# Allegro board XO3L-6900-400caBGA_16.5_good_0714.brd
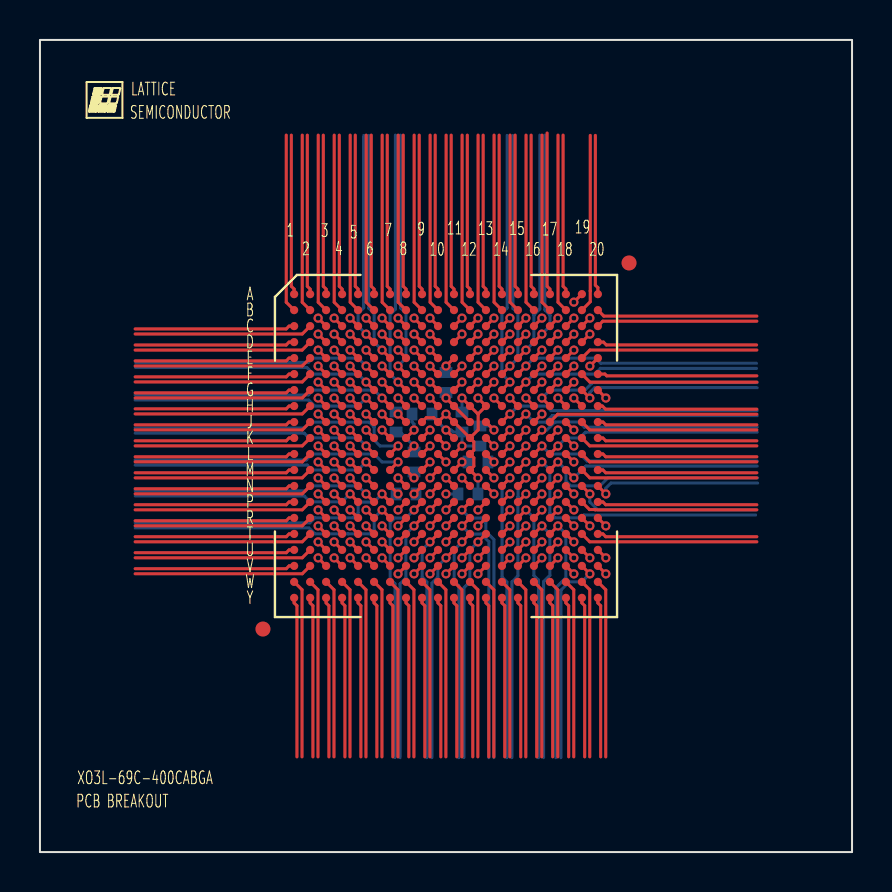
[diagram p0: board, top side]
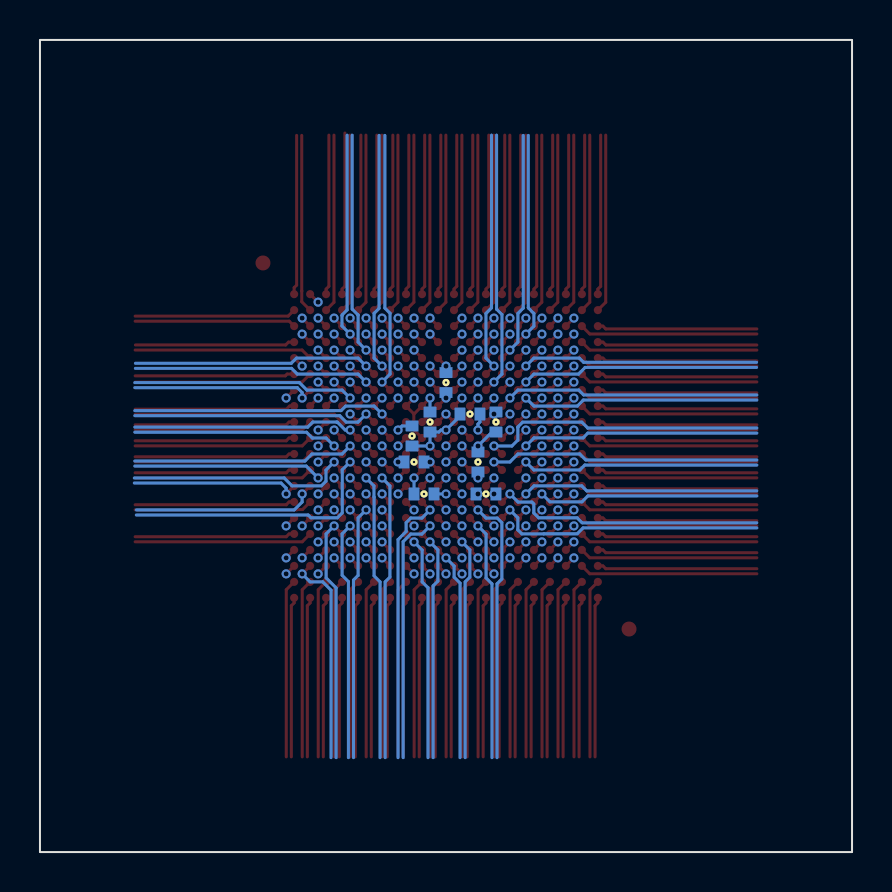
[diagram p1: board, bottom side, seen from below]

Outline 40.64 x 40.64 mm; copper layers: TOP, L2_GND, L3_SIGNAL, L4_SIGNAL, L5_PWR, BOTTOM. Coordinates in mm from the lower left corner of the outline.
Outline path: rectangle 0,0 40.64,40.64

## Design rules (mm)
net group CDPB4: nets PB4C PB4D
net group CDPB6: nets PB6C PB6D
net group CDPB7: nets PB7C PB7D
net group CDPB9: nets PB9C PB9D
net group CDPB10: nets PB10C PB10D
net group CDPB12: nets PB12C PB12D
net group CDPB13: nets PB13C PB13D
net group CDPB15: nets PB15C PB15D
net group CDPB16: nets PB16C PB16D
net group CDPB18: nets PB18C PB18D
net group CDPB21: nets PB21C PB21D
net group CDPB23: nets PB23C PB23D
net group CDPB26: nets PB26C PB26D
net group CDPB28: nets PB28C PB28D
net group CDPB29: nets PB29C PB29D
net group CDPB31: nets PB31C PB31D
net group CDPB32: nets PB32C PB32D
net group CDPB34: nets PB34C PB34D
net group CDPB35: nets PB35C PB35D
net group CDPB37: nets PB37C PB37D
net group CDPB38: nets PB38C PB38D
net group CDPL2: nets PL2C PL2D
net group CDPL3: nets PL3C PL3D
net group CDPL4: nets PL4C PL4D
net group CDPL5: nets PL5C PL5D
net group CDPL6: nets PL6C PL6D
net group CDPL7: nets PL7C PL7D
net group CDPL8: nets PL8C PL8D
net group CDPL9: nets PL9C PL9D
net group CDPL10: nets PL10C PL10D
net group CDPL11: nets PL11C PL11D
net group CDPL12: nets PL12C PL12D
net group CDPL14: nets PL14C PL14D
net group CDPL15: nets PL15C PL15D
net group CDPL16: nets PL16C PL16D
net group CDPL17: nets PL17C PL17D
net group CDPL18: nets PL18C PL18D
net group CDPL19: nets PL19C PL19D
net group CDPL20: nets PL20C PL20D
net group CDPL21: nets PL21C PL21D
net group CDPL22: nets PL22C PL22D
net group CDPL23: nets PL23C PL23D
net group CDPL24: nets PL24C PL24D
net group CDPL25: nets PL25C PL25D
net group CDPL26: nets PL26C PL26D
net group CDPL29: nets PL29C PL29D
net group CDPL32: nets PL32C PL32D
net group CDPL35: nets PL35C PL35D
net group CDPL38: nets PL38C PL38D
net group CDPL41: nets PL41C PL41D
net group CDPL44: nets PL44C PL44D
net group CDPL47: nets PL47C PL47D
net group CDPL50: nets PL50C PL50D
net group CDPL53: nets PL53C PL53D
net group CDPL56: nets PL56C PL56D
net group CDPL59: nets PL59C PL59D
net group CDPL62: nets PL62C PL62D
net group CDPL65: nets PL65C PL65D
net group CDPL68: nets PL68C PL68D
net group CDPL71: nets PL71C PL71D
net group CDPL74: nets PL74C PL74D
net group CDPL77: nets PL77C PL77D
net group CDPL80: nets PL80C PL80D
net group CDPL83: nets PL83C PL83D
net group CDPL86: nets PL86C PL86D
net group CDPL89: nets PL89C PL89D
net group CDPL92: nets PL92C PL92D
net group CDPR2: nets PR2C PR2D
net group CDPR3: nets PR3C PR3D
net group CDPR4: nets PR4C PR4D
net group CDPR5: nets PR5C PR5D
net group CDPR6: nets PR6C PR6D
net group CDPR7: nets PR7C PR7D
net group CDPR8: nets PR8C PR8D
net group CDPR9: nets PR9C PR9D
net group CDPR10: nets PR10C PR10D
net group CDPR11: nets PR11C PR11D
net group CDPR12: nets PR12C PR12D
net group CDPR14: nets PR14C PR14D
net group CDPR15: nets PR15C PR15D
net group CDPR16: nets PR16C PR16D
net group CDPR17: nets PR17C PR17D
net group CDPR18: nets PR18C PR18D
net group CDPR19: nets PR19C PR19D
net group CDPR20: nets PR20C PR20D
net group CDPR21: nets PR21C PR21D
net group CDPR22: nets PR22C PR22D
net group CDPR23: nets PR23C PR23D
net group CDPR24: nets PR24C PR24D
net group CDPR25: nets PR25C PR25D
net group CDPR26: nets PR26C PR26D
net group CDPR29: nets PR29C PR29D
net group CDPR32: nets PR32C PR32D
net group CDPR35: nets PR35C PR35D
net group CDPR38: nets PR38C PR38D
net group CDPR41: nets PR41C PR41D
net group CDPR44: nets PR44C PR44D
net group CDPR47: nets PR47C PR47D
net group CDPR50: nets PR50C PR50D
net group CDPR53: nets PR53C PR53D
net group CDPR56: nets PR56C PR56D
net group CDPR59: nets PR59C PR59D
net group CDPR62: nets PR62C PR62D
net group CDPR65: nets PR65C PR65D
net group CDPR68: nets PR68C PR68D
net group CDPR71: nets PR71C PR71D
net group CDPR74: nets PR74C PR74D
net group CDPR77: nets PR77C PR77D
net group CDPR80: nets PR80C PR80D
net group CDPR83: nets PR83C PR83D
net group CDPR86: nets PR86C PR86D
net group CDPR89: nets PR89C PR89D
net group CDPR92: nets PR92C PR92D
net group CDPT9: nets PT9C PT9D
net group CDPT10: nets PT10C PT10D
net group CDPT11: nets PT11C PT11D
net group CDPT12: nets PT12C PT12D
net group CDPT13: nets PT13C PT13D
net group CDPT14: nets PT14C PT14D
net group CDPT15: nets PT15C PT15D
net group CDPT16: nets PT16C PT16D
net group CDPT17: nets PT17C PT17D
net group CDPT18: nets PT18C PT18D
net group CDPT21: nets PT21C PT21D
net group CDPT22: nets PT22C PT22D
net group CDPT25: nets PT25C PT25D
net group CDPT26: nets PT26C PT26D
net group CDPT27: nets PT27C PT27D
net group CDPT28: nets PT28C PT28D
net group CDPT32: nets PT32C PT32D
net group CDPT33: nets PT33C PT33D
net group CDPT34: nets PT34C PT34D
net group CDPT35: nets PT35C PT35D
net group CDPT36: nets PT36C PT36D
net group PB4: nets PB4A PB4B
net group PB6: nets PB6A PB6B
net group PB7: nets PB7A PB7B
net group PB9: nets PB9A PB9B
net group PB10: nets PB10A PB10B
net group PB12: nets PB12A PB12B
net group PB13: nets PB13A PB13B
net group PB15: nets PB15A PB15B
net group PB16: nets PB16A PB16B
net group PB18: nets PB18A PB18B
net group PB21: nets PB21A PB21B
net group PB23: nets PB23A PB23B
net group PB26: nets PB26A PB26B
net group PB28: nets PB28A PB28B
net group PB29: nets PB29A PB29B
net group PB31: nets PB31A PB31B
net group PB32: nets PB32A PB32B
net group PB34: nets PB34A PB34B
net group PB35: nets PB35A PB35B
net group PB37: nets PB37A PB37B
net group PB38: nets PB38A PB38B
net group PB98: nets PB98A PB98B
net group PL2: nets PL2A PL2B
net group PL3: nets PL3A PL3B
net group PL4: nets PL4A PL4B
net group PL5: nets PL5A PL5B
net group PL6: nets PL6A PL6B
net group PL7: nets PL7A PL7B
net group PL8: nets PL8A PL8B
net group PL9: nets PL9A PL9B
net group PL10: nets PL10A PL10B
net group PL11: nets PL11A PL11B
net group PL12: nets PL12A PL12B
net group PL14: nets PL14A PL14B
net group PL15: nets PL15A PL15B
net group PL16: nets PL16A PL16B
net group PL17: nets PL17A PL17B
net group PL18: nets PL18A PL18B
net group PL19: nets PL19A PL19B
net group PL20: nets PL20A PL20B
net group PL21: nets PL21A PL21B
net group PL22: nets PL22A PL22B
net group PL23: nets PL23A PL23B
net group PL24: nets PL24A PL24B
net group PL25: nets PL25A PL25B
net group PL29: nets PL29A PL29B
net group PL32: nets PL32A PL32B
net group PL35: nets PL35A PL35B
net group PL38: nets PL38A PL38B
net group PL41: nets PL41A PL41B
net group PL44: nets PL44A PL44B
net group PL47: nets PL47A PL47B
net group PL50: nets PL50A PL50B
net group PL53: nets PL53A PL53B
net group PL56: nets PL56A PL56B
net group PL59: nets PL59A PL59B
net group PL62: nets PL62A PL62B
net group PL65: nets PL65A PL65B
net group PL68: nets PL68A PL68B
net group PL71: nets PL71A PL71B
net group PL74: nets PL74A PL74B
net group PL77: nets PL77A PL77B
net group PL80: nets PL80A PL80B
net group PL83: nets PL83A PL83B
net group PL86: nets PL86A PL86B
net group PL89: nets PL89A PL89B
net group PL92: nets PL92A PL92B
net group PR2: nets PR2A PR2B
net group PR3: nets PR3A PR3B
net group PR4: nets PR4A PR4B
net group PR5: nets PR5A PR5B
net group PR6: nets PR6A PR6B
net group PR7: nets PR7A PR7B
net group PR8: nets PR8A PR8B
net group PR9: nets PR9A PR9B
net group PR10: nets PR10A PR10B
net group PR11: nets PR11A PR11B
net group PR12: nets PR12A PR12B
net group PR14: nets PR14A PR14B
net group PR15: nets PR15A PR15B
net group PR16: nets PR16A PR16B
net group PR17: nets PR17A PR17B
net group PR18: nets PR18A PR18B
net group PR19: nets PR19A PR19B
net group PR20: nets PR20A PR20B
net group PR21: nets PR21A PR21B
net group PR22: nets PR22A PR22B
net group PR23: nets PR23A PR23B
net group PR24: nets PR24A PR24B
net group PR25: nets PR25A PR25B
net group PR26: nets PR26A PR26B
net group PR29: nets PR29A PR29B
net group PR32: nets PR32A PR32B
net group PR35: nets PR35A PR35B
net group PR38: nets PR38A PR38B
net group PR41: nets PR41A PR41B
net group PR44: nets PR44A PR44B
net group PR47: nets PR47A PR47B
net group PR50: nets PR50A PR50B
net group PR53: nets PR53A PR53B
net group PR56: nets PR56A PR56B
net group PR59: nets PR59A PR59B
net group PR62: nets PR62A PR62B
net group PR65: nets PR65A PR65B
net group PR68: nets PR68A PR68B
net group PR71: nets PR71A PR71B
net group PR74: nets PR74A PR74B
net group PR77: nets PR77A PR77B
net group PR80: nets PR80A PR80B
net group PR83: nets PR83A PR83B
net group PR86: nets PR86A PR86B
net group PR89: nets PR89A PR89B
net group PR92: nets PR92A PR92B
net group PT4: nets PT4A PT4B
net group PT6: nets PT6A PT6B
net group PT9: nets PT9A PT9B
net group PT10: nets PT10A PT10B
net group PT11: nets PT11A PT11B
net group PT12: nets PT12A PT12B
net group PT13: nets PT13A PT13B
net group PT14: nets PT14A PT14B
net group PT15: nets PT15A PT15B
net group PT16: nets PT16A PT16B
net group PT17: nets PT17A PT17B
net group PT18: nets PT18A PT18B
net group PT20: nets PT20A PT20B
net group PT21: nets PT21A PT21B
net group PT22: nets PT22A PT22B
net group PT24: nets PT24A PT24B
net group PT25: nets PT25A PT25B
net group PT26: nets PT26A PT26B
net group PT27: nets PT27A PT27B
net group PT28: nets PT28A PT28B
net group PT29: nets PT29A PT29B
net group PT31: nets PT31A PT31B
net group PT32: nets PT32A PT32B
net group PT33: nets PT33A PT33B
net group PT34: nets PT34A PT34B
net group PT35: nets PT35A PT35B
net group PT36: nets PT36A PT36B
net group PT38: nets PT38A PT38B
net group PT40: nets PT40A PT40B
net group PT42: nets PT42A PT42B
net group PT44: nets PT44A PT44B
net group PT45: nets PT45A PT45B
net group PT47: nets PT47A PT47B
net group PT49: nets PT49A PT49B
net group PT51: nets PT51A PT51B
net group PT54: nets PT54A PT54B
net group PT56: nets PT56A PT56B
net group PT58: nets PT58A PT58B
net group PT60: nets PT60A PT60B
net group PT63: nets PT63A PT63B
net group PT65: nets PT65A PT65B
net group PT69: nets PT69A PT69B
net group PT71: nets PT71A PT71B
net group PT74: nets PT74A PT74B
net group PT76: nets PT76A PT76B
net group PT101: nets PT101A PT101B
net group PT103: nets PT103A PT103B
net group PT105: nets PT105A PT105B
net group PT107: nets PT107A PT107B
net group PT110: nets PT110A PT110B
net group PT112: nets PT112A PT112B
net group PT114: nets PT114A PT114B
net group PT116: nets PT116A PT116B
net group PT119: nets PT119A PT119B
net group PT121: nets PT121A PT121B

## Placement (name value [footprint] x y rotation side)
BGA  -  [BGA400C80P20X20_1700X1700X13-1]  20.32 20.32 270 top
C1  VAL  [C0402]  20.32 23.5 270 bottom
C2  VAL  [C0402]  18.32 17.92 0 bottom
C3  VAL  [C0402]  17.82 21.52 90 bottom
C4  VAL  [C0402]  21.12 21.52 270 bottom
C5  VAL  [C0402]  21.92 19.52 180 bottom
C6  VAL  [C0402]  22.02 20.82 90 bottom
C7  VAL  [C0402]  21.42 17.92 180 bottom
C11  VAL  [C0402]  18.72 19.52 90 bottom
C12  VAL  [C0402]  19.12 21.92 180 bottom
NOREF  -  []  24.69 13 0 top

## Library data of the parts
BGA = BGA400C80P20X20_1700X1700X13-1
C1 C4-C7 C11 C12 = C0402: Tolerance: TOL; User Part Number: UPN
C2 C3 = C0402: User Part Number: UPN; Tolerance: TOL

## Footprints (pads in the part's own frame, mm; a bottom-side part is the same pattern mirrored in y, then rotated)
BGA400C80P20X20_1700X1700X13-1
  round 0.75 smd: (-9.16,9.16) (9.16,-9.16)
  round 0.406 smd: A1(-7.6,-7.6) A2(-7.6,-6.8) A3(-7.6,-6) A4(-7.6,-5.2) A5(-7.6,-4.4) A6(-7.6,-3.6) A7(-7.6,-2.8) A8(-7.6,-2) A9(-7.6,-1.2) A10(-7.6,-0.4) A11(-7.6,0.4) A12(-7.6,1.2) A13(-7.6,2) A14(-7.6,2.8) A15(-7.6,3.6) A16(-7.6,4.4) A17(-7.6,5.2) A18(-7.6,6) A19(-7.6,6.8) A20(-7.6,7.6) B1(-6.8,-7.6) B2(-6.8,-6.8) B3(-6.8,-6) B4(-6.8,-5.2) B5(-6.8,-4.4) B6(-6.8,-3.6) B7(-6.8,-2.8) B8(-6.8,-2) B9(-6.8,-1.2) B10(-6.8,-0.4) B11(-6.8,0.4) B12(-6.8,1.2) B13(-6.8,2) B14(-6.8,2.8) B15(-6.8,3.6) B16(-6.8,4.4) B17(-6.8,5.2) B18(-6.8,6) B19(-6.8,6.8) B20(-6.8,7.6) C1(-6,-7.6) C2(-6,-6.8) C3(-6,-6) C4(-6,-5.2) C5(-6,-4.4) C6(-6,-3.6) C7(-6,-2.8) C8(-6,-2) C9(-6,-1.2) C10(-6,-0.4) C11(-6,0.4) C12(-6,1.2) C13(-6,2) C14(-6,2.8) C15(-6,3.6) C16(-6,4.4) C17(-6,5.2) C18(-6,6) C19(-6,6.8) C20(-6,7.6) D1(-5.2,-7.6) D2(-5.2,-6.8) D3(-5.2,-6) D4(-5.2,-5.2) D5(-5.2,-4.4) D6(-5.2,-3.6) D7(-5.2,-2.8) D8(-5.2,-2) D9(-5.2,-1.2) D10(-5.2,-0.4) D11(-5.2,0.4) D12(-5.2,1.2) D13(-5.2,2) D14(-5.2,2.8) D15(-5.2,3.6) D16(-5.2,4.4) D17(-5.2,5.2) D18(-5.2,6) D19(-5.2,6.8) D20(-5.2,7.6) E1(-4.4,-7.6) E2(-4.4,-6.8) E3(-4.4,-6) E4(-4.4,-5.2) E5(-4.4,-4.4) E6(-4.4,-3.6) E7(-4.4,-2.8) E8(-4.4,-2) E9(-4.4,-1.2) E10(-4.4,-0.4) E11(-4.4,0.4) E12(-4.4,1.2) E13(-4.4,2) E14(-4.4,2.8) E15(-4.4,3.6) E16(-4.4,4.4) E17(-4.4,5.2) E18(-4.4,6) E19(-4.4,6.8) E20(-4.4,7.6) F1(-3.6,-7.6) F2(-3.6,-6.8) F3(-3.6,-6) F4(-3.6,-5.2) F5(-3.6,-4.4) F6(-3.6,-3.6) F7(-3.6,-2.8) F8(-3.6,-2) F9(-3.6,-1.2) F10(-3.6,-0.4) F11(-3.6,0.4) F12(-3.6,1.2) F13(-3.6,2) F14(-3.6,2.8) F15(-3.6,3.6) F16(-3.6,4.4) F17(-3.6,5.2) F18(-3.6,6) F19(-3.6,6.8) F20(-3.6,7.6) G1(-2.8,-7.6) G2(-2.8,-6.8) G3(-2.8,-6) G4(-2.8,-5.2) G5(-2.8,-4.4) G6(-2.8,-3.6) G7(-2.8,-2.8) G8(-2.8,-2) G9(-2.8,-1.2) G10(-2.8,-0.4) G11(-2.8,0.4) G12(-2.8,1.2) G13(-2.8,2) G14(-2.8,2.8) G15(-2.8,3.6) G16(-2.8,4.4) G17(-2.8,5.2) G18(-2.8,6) G19(-2.8,6.8) G20(-2.8,7.6) H1(-2,-7.6) H2(-2,-6.8) H3(-2,-6) H4(-2,-5.2) H5(-2,-4.4) H6(-2,-3.6) H7(-2,-2.8) H8(-2,-2) H9(-2,-1.2) H10(-2,-0.4) H11(-2,0.4) H12(-2,1.2) H13(-2,2) H14(-2,2.8) H15(-2,3.6) H16(-2,4.4) H17(-2,5.2) H18(-2,6) H19(-2,6.8) H20(-2,7.6) J1(-1.2,-7.6) J2(-1.2,-6.8) J3(-1.2,-6) J4(-1.2,-5.2) J5(-1.2,-4.4) J6(-1.2,-3.6) J7(-1.2,-2.8) J8(-1.2,-2) J9(-1.2,-1.2) J10(-1.2,-0.4) J11(-1.2,0.4) J12(-1.2,1.2) J13(-1.2,2) J14(-1.2,2.8) J15(-1.2,3.6) J16(-1.2,4.4) J17(-1.2,5.2) J18(-1.2,6) J19(-1.2,6.8) J20(-1.2,7.6) K1(-0.4,-7.6) K2(-0.4,-6.8) K3(-0.4,-6) K4(-0.4,-5.2) K5(-0.4,-4.4) K6(-0.4,-3.6) K7(-0.4,-2.8) K8(-0.4,-2) K9(-0.4,-1.2) K10(-0.4,-0.4) K11(-0.4,0.4) K12(-0.4,1.2) K13(-0.4,2) K14(-0.4,2.8) K15(-0.4,3.6) K16(-0.4,4.4) K17(-0.4,5.2) K18(-0.4,6) K19(-0.4,6.8) K20(-0.4,7.6) L1(0.4,-7.6) L2(0.4,-6.8) L3(0.4,-6) L4(0.4,-5.2) L5(0.4,-4.4) L6(0.4,-3.6) L7(0.4,-2.8) L8(0.4,-2) L9(0.4,-1.2) L10(0.4,-0.4) L11(0.4,0.4) L12(0.4,1.2) L13(0.4,2) L14(0.4,2.8) L15(0.4,3.6) L16(0.4,4.4) L17(0.4,5.2) L18(0.4,6) L19(0.4,6.8) L20(0.4,7.6) M1(1.2,-7.6) M2(1.2,-6.8) M3(1.2,-6) M4(1.2,-5.2) M5(1.2,-4.4) M6(1.2,-3.6) M7(1.2,-2.8) M8(1.2,-2) M9(1.2,-1.2) M10(1.2,-0.4) M11(1.2,0.4) M12(1.2,1.2) M13(1.2,2) M14(1.2,2.8) M15(1.2,3.6) M16(1.2,4.4) M17(1.2,5.2) M18(1.2,6) M19(1.2,6.8) M20(1.2,7.6) N1(2,-7.6) N2(2,-6.8) N3(2,-6) N4(2,-5.2) N5(2,-4.4) N6(2,-3.6) N7(2,-2.8) N8(2,-2) N9(2,-1.2) N10(2,-0.4) N11(2,0.4) N12(2,1.2) N13(2,2) N14(2,2.8) N15(2,3.6) N16(2,4.4) N17(2,5.2) N18(2,6) N19(2,6.8) N20(2,7.6) P1(2.8,-7.6) P2(2.8,-6.8) P3(2.8,-6) P4(2.8,-5.2) P5(2.8,-4.4) P6(2.8,-3.6) P7(2.8,-2.8) P8(2.8,-2) P9(2.8,-1.2) P10(2.8,-0.4) P11(2.8,0.4) P12(2.8,1.2) P13(2.8,2) P14(2.8,2.8) P15(2.8,3.6) P16(2.8,4.4) P17(2.8,5.2) P18(2.8,6) P19(2.8,6.8) P20(2.8,7.6) R1(3.6,-7.6) R2(3.6,-6.8) R3(3.6,-6) R4(3.6,-5.2) R5(3.6,-4.4) R6(3.6,-3.6) R7(3.6,-2.8) R8(3.6,-2) R9(3.6,-1.2) R10(3.6,-0.4) R11(3.6,0.4) R12(3.6,1.2) R13(3.6,2) R14(3.6,2.8) R15(3.6,3.6) R16(3.6,4.4) R17(3.6,5.2) R18(3.6,6) R19(3.6,6.8) R20(3.6,7.6) T1(4.4,-7.6) T2(4.4,-6.8) T3(4.4,-6) T4(4.4,-5.2) T5(4.4,-4.4) T6(4.4,-3.6) T7(4.4,-2.8) T8(4.4,-2) T9(4.4,-1.2) T10(4.4,-0.4) T11(4.4,0.4) T12(4.4,1.2) T13(4.4,2) T14(4.4,2.8) T15(4.4,3.6) T16(4.4,4.4) T17(4.4,5.2) T18(4.4,6) T19(4.4,6.8) T20(4.4,7.6) U1(5.2,-7.6) U2(5.2,-6.8) U3(5.2,-6) U4(5.2,-5.2) U5(5.2,-4.4) U6(5.2,-3.6) U7(5.2,-2.8) U8(5.2,-2) U9(5.2,-1.2) U10(5.2,-0.4) U11(5.2,0.4) U12(5.2,1.2) U13(5.2,2) U14(5.2,2.8) U15(5.2,3.6) U16(5.2,4.4) U17(5.2,5.2) U18(5.2,6) U19(5.2,6.8) U20(5.2,7.6) V1(6,-7.6) V2(6,-6.8) V3(6,-6) V4(6,-5.2) V5(6,-4.4) V6(6,-3.6) V7(6,-2.8) V8(6,-2) V9(6,-1.2) V10(6,-0.4) V11(6,0.4) V12(6,1.2) V13(6,2) V14(6,2.8) V15(6,3.6) V16(6,4.4) V17(6,5.2) V18(6,6) V19(6,6.8) V20(6,7.6) W1(6.8,-7.6) W2(6.8,-6.8) W3(6.8,-6) W4(6.8,-5.2) W5(6.8,-4.4) W6(6.8,-3.6) W7(6.8,-2.8) W8(6.8,-2) W9(6.8,-1.2) W10(6.8,-0.4) W11(6.8,0.4) W12(6.8,1.2) W13(6.8,2) W14(6.8,2.8) W15(6.8,3.6) W16(6.8,4.4) W17(6.8,5.2) W18(6.8,6) W19(6.8,6.8) W20(6.8,7.6) Y1(7.6,-7.6) Y2(7.6,-6.8) Y3(7.6,-6) Y4(7.6,-5.2) Y5(7.6,-4.4) Y6(7.6,-3.6) Y7(7.6,-2.8) Y8(7.6,-2) Y9(7.6,-1.2) Y10(7.6,-0.4) Y11(7.6,0.4) Y12(7.6,1.2) Y13(7.6,2) Y14(7.6,2.8) Y15(7.6,3.6) Y16(7.6,4.4) Y17(7.6,5.2) Y18(7.6,6) Y19(7.6,6.8) Y20(7.6,7.6)
C0402
  rect 0.54x0.64 smd: 1(-0.5,0) 2(0.5,0)

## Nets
GND: BGA.C5 BGA.D3 BGA.D4 BGA.E5 BGA.E9 BGA.E10 BGA.E11 BGA.E12 BGA.E13 BGA.E16 BGA.E18 BGA.G18 BGA.H5 BGA.K3 BGA.K10 BGA.K11 BGA.L8 BGA.L10 BGA.L11 BGA.L18 BGA.M11 BGA.N7 BGA.R18 BGA.T15 BGA.U3 BGA.U7 BGA.U8 BGA.U13 BGA.U16 BGA.V5 BGA.V7 BGA.V11 BGA.V18 C1.1 C2.1 C3.1 C4.2 C5.2 C6.1 C7.2 C11.2 C12.1
VCC: BGA.H12 BGA.H13 BGA.J9 BGA.J10 BGA.J11 BGA.K12 BGA.L9 BGA.L12 BGA.M10 BGA.M12 C4.1 C7.1
VCCIO0: BGA.H8 BGA.H9 BGA.H10 BGA.H11 BGA.J12 C1.2
VCCIO1: BGA.J13 BGA.K13 BGA.L13 BGA.M13 BGA.N13 C5.1 C6.2
VCCIO2: BGA.N8 BGA.N9 BGA.N10 BGA.N11 BGA.N12 C2.2
VCCIO3: BGA.M8 BGA.M9 C11.1
VCCIO4: BGA.K8 BGA.K9 C12.2
VCCIO5: BGA.J7 BGA.J8 C3.2
PB4A: BGA.W1
PB4B: BGA.Y1
PB4C: BGA.R6
PB4D: BGA.T6
PB6A: BGA.W2
PB6B: BGA.Y2
PB6C: BGA.P7
PB6D: BGA.R7
PB7A: BGA.W3
PB7B: BGA.Y3
PB7C: BGA.V6
PB7D: BGA.U6
PB9A: BGA.W4
PB9B: BGA.Y4
PB9C: BGA.P8
PB9D: BGA.R8
PB10A: BGA.W5
PB10B: BGA.Y5
PB10C: BGA.T7
PB10D: BGA.T8
PB12A: BGA.W6
PB12B: BGA.Y6
PB12C: BGA.P9
PB12D: BGA.R9
PB13A: BGA.W7
PB13B: BGA.Y7
PB13C: BGA.V8
PB13D: BGA.U9
PB15A: BGA.W8
PB15B: BGA.Y8
PB15C: BGA.V9
PB15D: BGA.T9
PB16A: BGA.W9
PB16B: BGA.Y9
PB16C: BGA.P10
PB16D: BGA.R10
PB18A: BGA.Y10
PB18B: BGA.W10
PB18C: BGA.U10
PB18D: BGA.V10
PB21A: BGA.Y11
PB21B: BGA.W11
PB21C: BGA.U11
PB21D: BGA.T10
PB23A: BGA.Y12
PB23B: BGA.W12
PB23C: BGA.P11
PB23D: BGA.R11
PB26A: BGA.Y13
PB26B: BGA.W13
PB26C: BGA.V12
PB26D: BGA.V13
PB28A: BGA.Y14
PB28B: BGA.W14
PB28C: BGA.U12
PB28D: BGA.T11
PB29A: BGA.Y15
PB29B: BGA.W15
PB29C: BGA.P12
PB29D: BGA.R12
PB31A: BGA.Y16
PB31B: BGA.W16
PB31C: BGA.T12
PB31D: BGA.T13
PB32A: BGA.Y17
PB32B: BGA.W17
PB32C: BGA.P13
PB32D: BGA.R13
PB34A: BGA.V14
PB34B: BGA.U14
PB34C: BGA.V15
PB34D: BGA.V16
PB35A: BGA.Y18
PB35B: BGA.W18
PB35C: BGA.T14
PB35D: BGA.U15
PB37A: BGA.Y19
PB37B: BGA.W19
PB37C: BGA.P14
PB37D: BGA.R14
PB38A: BGA.Y20
PB38B: BGA.W20
PB38C: BGA.T16
PB38D: BGA.R15
PL2A: BGA.C4
PL2B: BGA.C3
PL2C: BGA.F6
PL2D: BGA.G6
PL3A: BGA.C2
PL3B: BGA.C1
PL3C: BGA.E4
PL3D: BGA.E3
PL4A: BGA.D2
PL4B: BGA.D1
PL4C: BGA.F5
PL4D: BGA.G5
PL5A: BGA.F4
PL5B: BGA.F3
PL5C: BGA.H6
PL5D: BGA.H7
PL6A: BGA.E2
PL6B: BGA.E1
PL6C: BGA.F2
PL6D: BGA.F1
PL7A: BGA.G4
PL7B: BGA.G3
PL7C: BGA.H3
PL7D: BGA.H4
PL8A: BGA.G2
PL8B: BGA.G1
PL8C: BGA.J6
PL8D: BGA.J5
PL9A: BGA.H2
PL9B: BGA.H1
PL9C: BGA.J4
PL9D: BGA.J3
PL10A: BGA.J2
PL10B: BGA.J1
PL10C: BGA.K5
PL10D: BGA.K4
PL11A: BGA.K2
PL11B: BGA.K1
PL11C: BGA.K6
PL11D: BGA.K7
PL12A: BGA.L1
PL12B: BGA.L2
PL12C: BGA.L3
PL12D: BGA.L4
PL15A: BGA.M1
PL15B: BGA.M2
PL15C: BGA.M3
PL15D: BGA.M4
PL16A: BGA.L5
PL16B: BGA.M5
PL16C: BGA.L6
PL16D: BGA.L7
PL17A: BGA.N1
PL17B: BGA.N2
PL17C: BGA.P1
PL17D: BGA.P2
PL18A: BGA.N3
PL18B: BGA.N4
PL18C: BGA.M6
PL18D: BGA.M7
PL19A: BGA.P3
PL19B: BGA.P4
PL19C: BGA.R1
PL19D: BGA.R2
PL21A: BGA.T1
PL21B: BGA.T2
PL21C: BGA.N5
PL21D: BGA.N6
PL22A: BGA.U1
PL22B: BGA.U2
PL22C: BGA.R3
PL22D: BGA.R4
PL23A: BGA.T3
PL23B: BGA.T4
PL23C: BGA.V1
PL23D: BGA.V2
PL24A: BGA.V3
PL24B: BGA.V4
PL24C: BGA.P5
PL24D: BGA.P6
PL25A: BGA.T5
PL25B: BGA.R5
PL25C: BGA.U4
PL25D: BGA.U5
PR2A: BGA.D17
PR2B: BGA.C18
PR2C: BGA.F15
PR2D: BGA.G15
PR3A: BGA.C19
PR3B: BGA.E17
PR3C: BGA.F16
PR3D: BGA.D18
PR4A: BGA.B20
PR4B: BGA.C20
PR4C: BGA.H14
PR4D: BGA.H15
PR5A: BGA.D19
PR5B: BGA.F17
PR5C: BGA.D20
PR5D: BGA.E19
PR6A: BGA.G16
PR6B: BGA.F18
PR6C: BGA.G17
PR6D: BGA.E20
PR7A: BGA.F19
PR7B: BGA.F20
PR7C: BGA.J14
PR7D: BGA.J15
PR8A: BGA.G19
PR8B: BGA.H17
PR8C: BGA.H16
PR8D: BGA.G20
PR9A: BGA.H18
PR9B: BGA.H19
PR9C: BGA.J17
PR9D: BGA.H20
PR10A: BGA.J18
PR10B: BGA.J16
PR10C: BGA.K14
PR10D: BGA.K15
PR11A: BGA.J19
PR11B: BGA.J20
PR11C: BGA.K17
PR11D: BGA.K18
PR12A: BGA.K19
PR12B: BGA.K20
PR12C: BGA.K16
PR12D: BGA.L17
PR15A: BGA.L19
PR15B: BGA.L20
PR15C: BGA.L14
PR15D: BGA.L15
PR16A: BGA.M20
PR16B: BGA.M19
PR16C: BGA.L16
PR16D: BGA.M18
PR17A: BGA.M17
PR17B: BGA.N20
PR17C: BGA.M16
PR17D: BGA.N19
PR18A: BGA.N18
PR18B: BGA.N17
PR18C: BGA.P20
PR18D: BGA.P19
PR19A: BGA.P18
PR19B: BGA.R20
PR19C: BGA.M15
PR19D: BGA.M14
PR21A: BGA.N16
PR21B: BGA.R19
PR21C: BGA.T20
PR21D: BGA.T19
PR22A: BGA.U20
PR22B: BGA.P17
PR22C: BGA.T18
PR22D: BGA.U19
PR23A: BGA.V20
PR23B: BGA.P16
PR23C: BGA.N15
PR23D: BGA.N14
PR24A: BGA.R17
PR24B: BGA.U18
PR24C: BGA.P15
PR24D: BGA.R16
PR25A: BGA.V19
PR25B: BGA.T17
PR25C: BGA.U17
PR25D: BGA.V17
PT9A: BGA.B1
PT9B: BGA.A1
PT9C: BGA.G7
PT9D: BGA.F7
PT10A: BGA.B2
PT10B: BGA.A2
PT10C: BGA.E6
PT10D: BGA.D5
PT11A: BGA.B3
PT11B: BGA.A3
PT11C: BGA.D6
PT11D: BGA.E7
PT12A: BGA.B4
PT12B: BGA.A4
PT12C: BGA.C6
PT12D: BGA.D7
PT13A: BGA.B5
PT13B: BGA.A5
PT13C: BGA.G8
PT13D: BGA.F8
PT14A: BGA.B6
PT14B: BGA.A6
PT14C: BGA.E8
PT14D: BGA.C7
PT15A: BGA.B7
PT15B: BGA.A7
PT15C: BGA.G9
PT15D: BGA.F9
PT16A: BGA.B8
PT16B: BGA.A8
PT16C: BGA.D8
PT16D: BGA.C8
PT17A: BGA.B9
PT17B: BGA.A9
PT17C: BGA.C9
PT17D: BGA.D9
PT18A: BGA.B10
PT18B: BGA.A10
PT18C: BGA.G10
PT18D: BGA.F10
PT21A: BGA.B11
PT21B: BGA.A11
PT21C: BGA.D10
PT21D: BGA.C10
PT22A: BGA.A12
PT22B: BGA.B12
PT22C: BGA.C11
PT22D: BGA.D11
PT25A: BGA.A13
PT25B: BGA.B13
PT25C: BGA.G11
PT25D: BGA.F11
PT26A: BGA.A14
PT26B: BGA.B14
PT26C: BGA.D12
PT26D: BGA.C12
PT27A: BGA.A15
PT27B: BGA.B15
PT27C: BGA.C13
PT27D: BGA.D13
PT28A: BGA.A16
PT28B: BGA.B16
PT28C: BGA.G12
PT28D: BGA.F12
PT32A: BGA.A17
PT32B: BGA.B17
PT32C: BGA.C14
PT32D: BGA.D14
PT33A: BGA.C15
PT33B: BGA.C16
PT33C: BGA.G13
PT33D: BGA.F13
PT34A: BGA.A18
PT34B: BGA.B18
PT34C: BGA.E14
PT34D: BGA.D15
PT35A: BGA.E15
PT35B: BGA.D16
PT35C: BGA.G14
PT35D: BGA.F14
PT36A: BGA.B19
PT36B: BGA.A20
PT36C: BGA.C17
PT36D: BGA.A19

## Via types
v1: diameter 0.457, hole 0.254, TOP to BOTTOM, 266 vias

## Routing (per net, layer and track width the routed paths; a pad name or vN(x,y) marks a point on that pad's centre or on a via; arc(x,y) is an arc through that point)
GND: length 24.9
  TOP w0.152: BGA.V5 v1(15.52,14.72) ; BGA.U8 v1(17.92,14.72) ; BGA.L8 v1(18.72,20.32) ; BGA.L18 v1(26.72,19.52) ; BGA.U7 v1(17.12,15.52) ; BGA.K3 v1(13.92,21.12) ; BGA.C5 v1(15.52,26.72) ; BGA.K10 v1(20.32,20.32) ; BGA.E13 v1(22.72,25.12) ; BGA.E5 v1(15.52,25.12) ; BGA.D4 v1(14.72,25.92) ; BGA.V7 v1(17.12,14.72) ; BGA.V18 v1(26.72,13.92) ; BGA.H5 v1(15.52,22.72) ; BGA.E12 v1(21.92,25.12) ; BGA.T15 v1(24.32,16.32) ; BGA.M11 v1(21.12,19.52) ; BGA.E10 v1(19.52,25.12) ; BGA.E18 v1(26.72,25.12) ; BGA.N7 v1(17.92,17.92) ; BGA.L11 v1(21.12,20.32) ; BGA.D3 v1(13.92,25.92) ; BGA.R18 v1(26.72,16.32) ; BGA.E9 v1(18.72,25.12) ; BGA.U16 v1(25.12,15.52) ; BGA.U13 v1(21.92,14.72) ; BGA.G18 v1(26.72,23.52) ; BGA.K11 v1(20.32,21.12) ; BGA.E16 v1(25.12,25.12) ; BGA.U3 v1(13.92,15.52) ; BGA.V11 v1(20.32,13.92) ; BGA.L10 v1(20.32,19.52) ; BGA.E11 v1(20.32,24.32)
  BOTTOM w0.152: C1.1 v1(20.32,24.32) ; C12.1 19.62,21.82 v1(20.32,21.12) 20.57,21.12 20.67,21.02 C4.2 v1(21.12,20.32) C6.1 ; C5.2 v1(21.12,19.52) ; C11.2 v1(18.72,20.32) 18.02,21.02 C3.1 ; v1(20.32,17.92) 20.82,17.92 C7.2
VCC: length 12.1
  TOP w0.152: 21.93,21.91 21.93,21.13 BGA.K12 ; 21.93,21.91 21.93,21.93 BGA.H13 v1(21.92,22.72) ; 21.93,21.91 BGA.H12 v1(21.12,22.72) ; BGA.L9 v1(19.52,20.32) ; BGA.K12 BGA.J11 v1(20.32,21.92) BGA.J10 19.7,21.74 19.34,21.74 BGA.J9 ; BGA.K12 21.71,20.53 21.71,20.11 BGA.L12 21.71,19.73 21.71,19.31 BGA.M12 v1(21.92,18.72) ; BGA.M10 v1(19.52,18.72)
  BOTTOM w0.152: C4.1 21.12,21.98 v1(21.12,22.72) ; C7.1 v1(21.92,18.72)
VCCIO0: length 3.7
  TOP w0.152: v1(20.32,22.72) BGA.H11 BGA.J12 ; BGA.H10 v1(19.52,22.72) ; BGA.H8 v1(17.92,22.72) ; BGA.H9 v1(18.72,22.72)
  BOTTOM w0.152: C1.2 v1(20.32,22.72)
VCCIO1: length 3.9
  TOP w0.152: BGA.J13 v1(22.72,21.12) ; BGA.K13 v1(22.72,20.32) ; BGA.M13 v1(22.72,18.72) ; BGA.N13 v1(22.72,17.92) ; BGA.L13 v1(22.72,19.52)
  BOTTOM w0.152: C6.2 22.52,21.32 v1(22.72,21.12) ; C5.1 v1(22.72,19.52)
VCCIO2: length 2.8
  TOP w0.152: BGA.N8 v1(17.92,18.72) ; BGA.N12 v1(21.12,18.72) ; BGA.N9 v1(18.72,17.92) ; BGA.N11 v1(20.32,18.72) ; BGA.N10 v1(19.52,17.92)
VCCIO3: length 1.7
  TOP w0.152: BGA.M8 v1(18.72,18.72) ; BGA.M9 v1(19.52,19.52)
  BOTTOM w0.152: C11.1 v1(18.72,18.72) 18.73,19.03
VCCIO4: length 2
  TOP w0.152: BGA.K8 v1(18.72,21.12) ; BGA.K9 v1(19.52,21.12)
  BOTTOM w0.152: C12.2 18.62,21.52 18.72,21.42 v1(18.72,21.12)
VCCIO5: length 1.1
  TOP w0.152: BGA.J7 v1(17.12,21.92) ; BGA.J8 v1(17.92,21.92)
PB4A: length 8.9
  TOP w0.152: BGA.W1 13.11,13.13 13.11,4.76
PB4B: length 8
  TOP w0.152: 12.86,4.76 12.86,12.33 12.72,12.47 BGA.Y1
PB4C: length 13.2
  TOP w0.152: BGA.R6 v1(16.32,17.12)
  L4_SIGNAL w0.152: 16.2,4.8 16.2,14.2 15.92,14.48 15.92,16.72 v1(16.32,17.12)
PB4D: length 12.4
  TOP w0.152: BGA.T6 v1(16.32,16.32)
  L4_SIGNAL w0.152: v1(16.32,16.32) BGA.T6 16.72,14.45 16.45,14.17 16.45,4.8
PB6A: length 8.9
  TOP w0.152: BGA.W2 13.91,13.13 13.91,4.76
PB6B: length 8
  TOP w0.152: BGA.Y2 13.52,12.47 13.66,12.33 13.66,4.76
PB6C: length 13.8
  TOP w0.152: BGA.P7 v1(17.12,17.92)
  BOTTOM w0.152: v1(17.12,17.92) 16.71,17.51 16.02,17.51 15.93,17.42 15.93,16.97 15.68,16.73 13.76,16.73 13.51,16.48 4.77,16.48
PB6D: length 13.9
  TOP w0.152: BGA.R7 v1(17.12,17.12)
  BOTTOM w0.152: 4.77,16.22 13.46,16.22 13.76,15.93 15.42,15.93 15.43,15.92 16.52,15.92 16.73,16.13 16.73,16.73 v1(17.12,17.12)
PB7A: length 8.9
  TOP w0.152: 14.71,4.76 14.71,13.13 BGA.W3
PB7B: length 8
  TOP w0.152: 14.46,4.76 14.46,12.33 14.32,12.47 BGA.Y3
PB7C: length 10.6
  TOP w0.152: BGA.V6 v1(16.32,14.72)
  L3_SIGNAL w0.152: v1(16.32,14.72) 16.32,14.35 16.25,14.28 16.25,4.75
PB7D: length 11.5
  TOP w0.152: BGA.U6 v1(16.32,15.52)
  L3_SIGNAL w0.152: v1(16.32,15.52) 15.92,15.12 15.92,14.38 15.99,14.31 15.99,4.75
PB9A: length 8.9
  TOP w0.152: 15.51,4.76 15.51,13.13 BGA.W4
PB9B: length 8
  TOP w0.152: 15.26,4.76 15.26,12.33 15.12,12.47 BGA.Y4
PB9C: length 13.2
  TOP w0.152: BGA.P8 v1(17.92,17.12)
  L4_SIGNAL w0.152: 17.8,4.8 17.8,13.43 17.52,13.72 17.52,16.72 v1(17.92,17.12)
PB9D: length 12.4
  TOP w0.152: BGA.R8 v1(17.92,16.32)
  L4_SIGNAL w0.152: v1(17.92,16.32) 18.32,15.92 18.32,13.71 18.06,13.45 18.06,4.8
PB10A: length 8.9
  TOP w0.152: BGA.W5 16.31,13.13 16.31,4.76
PB10B: length 8
  TOP w0.152: 16.06,4.76 16.06,12.33 15.92,12.47 BGA.Y5
PB10C: length 12.4
  TOP w0.152: BGA.T7 v1(17.12,16.32)
  L3_SIGNAL w0.152: v1(17.12,16.32) 16.72,15.92 16.72,14.53 16.97,14.28 16.97,4.75
PB10D: length 11.6
  TOP w0.152: BGA.T8 v1(17.92,15.52)
  L3_SIGNAL w0.152: 17.23,4.75 17.23,14.23 17.52,14.52 17.52,15.12 v1(17.92,15.52)
PB12A: length 8.9
  TOP w0.152: 17.11,4.76 17.11,13.13 BGA.W6
PB12B: length 8
  TOP w0.152: 16.86,4.76 16.86,12.33 16.72,12.47 BGA.Y6
PB12C: length 13.9
  TOP w0.152: BGA.P9 v1(18.72,17.12)
  BOTTOM w0.152: 17.77,4.72 17.77,13.42 17.53,13.66 17.53,16.48 17.76,16.71 18.31,16.71 v1(18.72,17.12)
PB12D: length 12.5
  TOP w0.152: BGA.R9 v1(18.72,16.32)
  BOTTOM w0.152: v1(18.72,16.32) 18.31,15.91 18.31,13.71 18.02,13.42 18.02,4.72
PB13A: length 8.9
  TOP w0.152: 17.91,4.76 17.91,13.13 BGA.W7
PB13B: length 8
  TOP w0.152: BGA.Y7 17.52,12.47 17.66,12.33 17.66,4.76
PB13C: length 9.8
  TOP w0.152: BGA.V8 v1(17.92,13.92)
  L3_SIGNAL w0.152: 17.98,4.75 17.98,13.52 17.92,13.58 v1(17.92,13.92)
PB13D: length 10.7
  TOP w0.152: BGA.U9 v1(18.72,14.72)
  L3_SIGNAL w0.152: v1(18.72,14.72) 18.32,14.32 18.32,13.58 18.23,13.5 18.23,4.75
PB15A: length 8.9
  TOP w0.152: 18.71,4.76 18.71,13.13 BGA.W8
PB15B: length 8
  TOP w0.152: BGA.Y8 18.32,12.47 18.46,12.33 18.46,4.76
PB15C: length 9.8
  TOP w0.152: BGA.V9 v1(18.72,13.92)
  L3_SIGNAL w0.152: v1(18.72,13.92) 18.72,13.57 18.76,13.53 18.76,4.75
PB15D: length 11.5
  TOP w0.152: BGA.T9 v1(18.72,15.52)
  L3_SIGNAL w0.152: v1(18.72,15.52) 19.12,15.12 19.12,13.61 19.02,13.5 19.02,4.75
PB16A: length 8.9
  TOP w0.152: 19.51,4.76 19.51,13.13 BGA.W9
PB16B: length 8
  TOP w0.152: 19.26,4.76 19.26,12.33 19.12,12.47 BGA.Y9
PB16C: length 13.2
  TOP w0.152: BGA.P10 v1(19.52,17.12)
  L4_SIGNAL w0.152: v1(19.52,17.12) 19.12,16.72 19.12,13.72 19.39,13.45 19.39,4.8
PB16D: length 12.4
  TOP w0.152: BGA.R10 v1(19.52,16.32)
  L4_SIGNAL w0.152: 19.64,4.8 19.64,13.46 19.92,13.74 19.92,15.92 v1(19.52,16.32)
PB18A: length 8
  TOP w0.152: 20.06,4.76 20.06,12.33 19.92,12.47 BGA.Y10
PB18B: length 8.9
  TOP w0.152: BGA.W10 20.31,13.13 20.31,4.76
PB18C: length 10.7
  TOP w0.152: BGA.U10 v1(19.52,14.72)
  L3_SIGNAL w0.152: v1(19.52,14.72) 19.92,14.32 19.92,13.54 19.84,13.46 19.84,4.75
PB18D: length 9.8
  TOP w0.152: BGA.V10 v1(19.52,13.92)
  L3_SIGNAL w0.152: 19.59,4.75 19.59,13.49 19.52,13.56 v1(19.52,13.92)
PB21A: length 8
  TOP w0.152: 20.86,4.76 20.86,12.33 20.72,12.47 BGA.Y11
PB21B: length 8.9
  TOP w0.152: BGA.W11 21.11,13.13 21.11,4.76
PB21C: length 10.9
  TOP w0.152: BGA.U11 v1(20.32,14.72)
  BOTTOM w0.152: v1(20.32,14.72) 19.91,14.31 19.91,13.76 19.62,13.46 19.62,4.72
PB21D: length 11.6
  TOP w0.152: BGA.T10 v1(19.52,15.52)
  BOTTOM w0.152: v1(19.52,15.52) 19.13,15.13 19.13,13.76 19.36,13.52 19.36,4.72
PB23A: length 8
  TOP w0.152: 21.66,4.76 21.66,12.33 21.52,12.47 BGA.Y12
PB23B: length 8.9
  TOP w0.152: BGA.W12 21.91,13.13 21.91,4.76
PB23C: length 14.7
  TOP w0.152: BGA.P11 v1(20.32,17.12)
  L3_SIGNAL w0.152: v1(20.32,17.12) 20.72,16.72 22.22,16.72 22.61,16.33 22.61,4.76
PB23D: length 13.8
  TOP w0.152: BGA.R11 v1(20.32,16.32)
  L3_SIGNAL w0.152: 22.36,4.76 22.36,15.64 22.08,15.91 21.97,15.91 21.96,15.92 20.72,15.92 v1(20.32,16.32)
PB26A: length 8
  TOP w0.152: BGA.Y13 22.32,12.47 22.46,12.33 22.46,4.76
PB26B: length 8.9
  TOP w0.152: 22.71,4.76 22.71,13.13 BGA.W13
PB26C: length 9.8
  TOP w0.152: BGA.V12 v1(21.12,13.92)
  L3_SIGNAL w0.152: 21.35,4.75 21.35,13.69 v1(21.12,13.92)
PB26D: length 9.9
  TOP w0.152: BGA.V13 v1(21.92,13.92)
  L3_SIGNAL w0.152: 21.61,4.75 21.61,13.61 v1(21.92,13.92)
PB28A: length 8
  TOP w0.152: BGA.Y14 23.12,12.47 23.26,12.33 23.26,4.76
PB28B: length 8.9
  TOP w0.152: 23.51,4.76 23.51,13.13 BGA.W14
PB28C: length 10.8
  TOP w0.152: BGA.U12 v1(21.12,14.72)
  L4_SIGNAL w0.152: v1(21.12,14.72) 21.52,14.32 21.52,13.76 21.23,13.47 21.23,4.8
PB28D: length 11.6
  TOP w0.152: BGA.T11 v1(20.32,15.52)
  L4_SIGNAL w0.152: v1(20.32,15.52) 20.72,15.12 20.72,13.7 20.98,13.44 20.98,4.8
PB29A: length 8
  TOP w0.152: 24.06,4.76 24.06,12.33 23.92,12.47 BGA.Y15
PB29B: length 8.9
  TOP w0.152: 24.31,4.76 24.31,13.13 BGA.W15
PB29C: length 14
  TOP w0.152: BGA.P12 v1(21.12,17.12)
  BOTTOM w0.152: v1(21.12,17.12) 21.53,16.71 22.08,16.71 22.31,16.48 22.31,16.04 22.72,15.64 22.72,4.72
PB29D: length 13
  TOP w0.152: BGA.R12 v1(21.12,16.32)
  BOTTOM w0.152: 22.47,4.72 22.47,15.53 22.08,15.91 21.53,15.91 v1(21.12,16.32)
PB31A: length 8
  TOP w0.152: BGA.Y16 24.72,12.47 24.86,12.33 24.86,4.76
PB31B: length 8.9
  TOP w0.152: BGA.W16 25.11,13.13 25.11,4.76
PB31C: length 11.6
  TOP w0.152: BGA.T12 v1(21.12,15.52)
  BOTTOM w0.152: 20.97,4.72 20.97,13.32 20.73,13.56 20.73,15.12 21.12,15.52 v1(21.12,15.52)
PB31D: length 11.7
  TOP w0.152: BGA.T13 v1(21.92,15.52)
  BOTTOM w0.152: 21.22,4.72 21.22,13.23 21.51,13.52 21.51,15.11 v1(21.92,15.52)
PB32A: length 8
  TOP w0.152: BGA.Y17 25.52,12.47 25.66,12.33 25.66,4.76
PB32B: length 8.9
  TOP w0.152: 25.91,4.76 25.91,13.13 BGA.W17
PB32C: length 13.4
  TOP w0.152: BGA.P13 v1(21.92,17.12)
  L4_SIGNAL w0.152: 22.02,4.82 22.02,13.02 22.57,13.58 22.57,16.47 v1(21.92,17.12)
PB32D: length 12.5
  TOP w0.152: BGA.R13 v1(21.92,16.32)
  L4_SIGNAL w0.152: 21.77,4.82 21.77,13.13 22.32,13.68 22.32,15.92 v1(21.92,16.32)
PB34A: length 10.6
  TOP w0.152: BGA.V14 v1(23.52,14.72)
  L3_SIGNAL w0.152: v1(23.52,14.72) 23.52,14.42 23.66,14.28 23.66,4.76
PB34B: length 11.5
  TOP w0.152: BGA.U14 v1(23.52,15.52)
  L3_SIGNAL w0.152: 23.91,4.76 23.91,15.13 v1(23.52,15.52)
PB34C: length 10.6
  TOP w0.152: BGA.V15 v1(24.32,14.72)
  L3_SIGNAL w0.152: 24.59,4.76 24.59,14.45 v1(24.32,14.72)
PB34D: length 10.6
  TOP w0.152: BGA.V16 v1(25.12,14.72)
  L3_SIGNAL w0.152: v1(25.12,14.72) 24.84,14.44 24.84,4.76
PB35A: length 8
  TOP w0.152: 26.46,4.76 26.46,12.33 26.32,12.47 BGA.Y18
PB35B: length 8.9
  TOP w0.152: BGA.W18 26.71,13.13 26.71,4.76
PB35C: length 12.5
  TOP w0.152: BGA.T14 v1(23.52,16.32)
  L3_SIGNAL w0.152: 22.87,4.76 22.87,15.91 23.27,16.32 v1(23.52,16.32)
PB35D: length 13
  TOP w0.152: BGA.U15 v1(24.32,15.52)
  L3_SIGNAL w0.152: v1(24.32,15.52) 23.92,15.92 23.23,15.92 23.12,15.81 23.12,4.76
PB37A: length 8
  TOP w0.152: BGA.Y19 27.12,12.47 27.26,12.33 27.26,4.76
PB37B: length 8.9
  TOP w0.152: 27.51,4.76 27.51,13.13 BGA.W19
PB37C: length 14
  TOP w0.152: BGA.P14 v1(23.52,17.92)
  L4_SIGNAL w0.152: 22.85,4.8 22.85,17.25 v1(23.52,17.92)
PB37D: length 13.1
  TOP w0.152: BGA.R14 v1(23.52,17.12)
  L4_SIGNAL w0.152: v1(23.52,17.12) 23.1,16.7 23.1,4.8
PB38A: length 8
  TOP w0.152: BGA.Y20 27.92,12.47 28.06,12.33 28.06,4.76
PB38B: length 8.9
  TOP w0.152: 28.31,4.76 28.31,13.13 BGA.W20
PB38C: length 12.5
  TOP w0.152: BGA.T16 v1(25.12,16.32)
  BOTTOM w0.152: 25.2,4.72 25.2,13.53 25.52,13.85 25.52,15.92 v1(25.12,16.32)
PB38D: length 13.2
  TOP w0.152: BGA.R15 v1(24.32,17.12)
  BOTTOM w0.152: 24.95,4.72 24.95,13.61 24.72,13.84 24.72,16.72 v1(24.32,17.12)
PL2A: length 9.8
  TOP w0.152: BGA.C4 v1(14.72,26.72)
  L3_SIGNAL w0.152: 14.41,35.86 14.41,27.03 v1(14.72,26.72)
PL2B: length 9.8
  TOP w0.152: BGA.C3 v1(13.92,26.72)
  L3_SIGNAL w0.152: 14.15,35.86 14.15,26.95 v1(13.92,26.72)
PL2C: length 12.4
  TOP w0.152: BGA.F6 v1(16.32,24.32)
  BOTTOM w0.152: 4.78,24.51 13.43,24.51 13.64,24.72 15.92,24.72 v1(16.32,24.32)
PL2D: length 12.4
  TOP w0.152: BGA.G6 v1(16.32,23.52)
  BOTTOM w0.152: v1(16.32,23.52) 15.92,23.92 13.69,23.92 13.35,24.25 4.78,24.25
PL3A: length 8.9
  TOP w0.152: 4.76,25.93 13.13,25.93 BGA.C2
PL3B: length 8
  TOP w0.152: 4.76,26.18 12.33,26.18 12.47,26.32 BGA.C1
PL3C: length 10.7
  TOP w0.152: BGA.E4 v1(14.72,25.12)
  L3_SIGNAL w0.152: 4.75,25.46 13.48,25.46 13.54,25.52 14.32,25.52 v1(14.72,25.12)
PL3D: length 9.8
  TOP w0.152: BGA.E3 v1(13.92,25.12)
  L3_SIGNAL w0.152: v1(13.92,25.12) 13.54,25.12 13.46,25.2 4.75,25.2
PL4A: length 8.9
  TOP w0.152: BGA.D2 13.12,25.12 4.76,25.12
PL4B: length 8
  TOP w0.152: BGA.D1 12.47,25.52 12.32,25.37 4.76,25.37
PL4C: length 11.5
  TOP w0.152: BGA.F5 v1(15.52,24.32)
  L4_SIGNAL w0.152: v1(15.52,24.32) 15.12,24.72 13.73,24.72 13.41,24.39 4.84,24.39
PL4D: length 11.5
  TOP w0.152: BGA.G5 v1(15.52,23.52)
  L4_SIGNAL w0.152: v1(15.52,23.52) 15.12,23.92 13.55,23.92 13.33,24.14 4.84,24.14
PL5A: length 10.7
  TOP w0.152: BGA.F4 v1(14.72,24.32)
  L3_SIGNAL w0.152: 4.77,24.72 14.32,24.72 v1(14.72,24.32)
PL5B: length 9.8
  TOP w0.152: BGA.F3 v1(13.92,24.32)
  L3_SIGNAL w0.152: 4.77,24.46 13.4,24.46 13.54,24.32 v1(13.92,24.32)
PL5C: length 12.4
  TOP w0.152: BGA.H6 v1(16.32,22.72)
  BOTTOM w0.152: 4.76,22.62 13.45,22.62 13.75,22.32 15.92,22.32 v1(16.32,22.72)
PL5D: length 13.2
  TOP w0.152: BGA.H7 v1(17.12,22.72)
  BOTTOM w0.152: v1(17.12,22.72) 16.72,23.12 13.68,23.12 13.43,22.87 4.76,22.87
PL6A: length 8.9
  TOP w0.152: BGA.E2 13.13,24.33 4.76,24.33
PL6B: length 8
  TOP w0.152: 4.76,24.58 12.33,24.58 12.47,24.72 BGA.E1
PL6C: length 8.9
  TOP w0.152: 4.76,23.53 13.13,23.53 BGA.F2
PL6D: length 8
  TOP w0.152: BGA.F1 12.47,23.92 12.33,23.78 4.76,23.78
PL7A: length 10.7
  TOP w0.152: BGA.G4 v1(14.72,23.52)
  L3_SIGNAL w0.152: v1(14.72,23.52) 14.32,23.92 13.47,23.92 13.42,23.87 4.77,23.87
PL7B: length 9.8
  TOP w0.152: BGA.G3 v1(13.92,23.52)
  L3_SIGNAL w0.152: 4.77,23.61 13.45,23.61 13.54,23.52 v1(13.92,23.52)
PL7C: length 9.7
  TOP w0.152: BGA.H3 v1(13.92,22.72)
  L3_SIGNAL w0.152: 4.77,22.8 13.44,22.8 13.52,22.72 v1(13.92,22.72)
PL7D: length 10.7
  TOP w0.152: BGA.H4 v1(14.72,22.72)
  L3_SIGNAL w0.152: v1(14.72,22.72) 14.32,23.12 13.55,23.12 13.49,23.06 4.77,23.06
PL8A: length 8.9
  TOP w0.152: 4.76,22.73 13.13,22.73 13.52,23.12 BGA.G2
PL8B: length 8
  TOP w0.152: BGA.G1 12.47,23.12 12.33,22.98 4.76,22.98
PL8C: length 13
  TOP w0.152: BGA.J6 v1(16.32,21.92)
  L4_SIGNAL w0.152: v1(16.32,21.92) 15.92,22.32 15.92,22.89 15.69,23.12 13.53,23.12 13.3,22.88 4.78,22.88
PL8D: length 11.6
  TOP w0.152: BGA.J5 v1(15.52,21.92)
  L4_SIGNAL w0.152: 4.78,22.63 13.26,22.63 13.56,22.32 15.12,22.32 v1(15.52,21.92)
PL9A: length 8.9
  TOP w0.152: BGA.H2 13.13,21.93 4.76,21.93
PL9B: length 8
  TOP w0.152: 4.76,22.18 12.33,22.18 12.47,22.32 BGA.H1
PL9C: length 10.6
  TOP w0.152: BGA.J4 v1(14.72,21.92)
  L3_SIGNAL w0.152: 4.8,22.32 13.5,22.32 13.51,22.31 14.08,22.31 14.23,22.17 14.47,22.17 v1(14.72,21.92)
PL9D: length 9.7
  TOP w0.152: BGA.J3 v1(13.92,21.92)
  L3_SIGNAL w0.152: 4.8,22.07 13.4,22.07 13.54,21.92 v1(13.92,21.92)
PL10A: length 8.9
  TOP w0.152: 4.76,21.13 13.13,21.13 BGA.J2
PL10B: length 8
  TOP w0.152: BGA.J1 12.47,21.52 12.33,21.38 4.76,21.38
PL10C: length 11.5
  TOP w0.152: BGA.K5 v1(15.52,21.12)
  L3_SIGNAL w0.152: 4.85,21.26 13.38,21.26 13.64,21.52 15.12,21.52 v1(15.52,21.12)
PL10D: length 10.7
  TOP w0.152: BGA.K4 v1(14.72,21.12)
  L3_SIGNAL w0.152: 4.85,21 13.38,21 13.66,20.72 14.32,20.72 v1(14.72,21.12)
PL11A: length 8.9
  TOP w0.152: 4.76,20.33 13.13,20.33 BGA.K2
PL11B: length 8
  TOP w0.152: 4.76,20.58 12.33,20.58 12.47,20.72 BGA.K1
PL11C: length 12.4
  TOP w0.152: BGA.K6 v1(16.32,21.12)
  L4_SIGNAL w0.152: 4.78,21 13.46,21 13.75,20.72 15.92,20.72 v1(16.32,21.12)
PL11D: length 13.2
  TOP w0.152: BGA.K7 v1(17.12,21.12)
  L4_SIGNAL w0.152: 4.78,21.26 13.42,21.26 13.68,21.52 16.72,21.52 v1(17.12,21.12)
PL12A: length 8
  TOP w0.152: 4.76,19.78 12.33,19.78 12.47,19.92 BGA.L1
PL12B: length 8.9
  TOP w0.152: BGA.L2 13.13,19.53 4.76,19.53
PL12C: length 9.7
  TOP w0.152: BGA.L3 v1(13.92,20.32)
  L3_SIGNAL w0.152: 4.83,20.24 13.46,20.24 13.54,20.32 v1(13.92,20.32)
PL12D: length 10.7
  TOP w0.152: BGA.L4 v1(14.72,20.32)
  L3_SIGNAL w0.152: v1(14.72,20.32) 14.32,19.92 13.57,19.92 13.51,19.99 4.83,19.99
PL15A: length 8
  TOP w0.152: 4.76,18.98 12.33,18.98 12.47,19.12 BGA.M1
PL15B: length 8.9
  TOP w0.152: BGA.M2 13.13,18.73 4.76,18.73
PL15C: length 9.7
  TOP w0.152: BGA.M3 v1(13.92,19.52)
  L3_SIGNAL w0.152: v1(13.92,19.52) 13.54,19.52 13.46,19.44 4.83,19.44
PL15D: length 10.7
  TOP w0.152: BGA.M4 v1(14.72,19.52)
  L3_SIGNAL w0.152: v1(14.72,19.52) 14.32,19.12 13.56,19.12 13.49,19.18 4.83,19.18
PL16A: length 11.6
  TOP w0.152: BGA.L5 v1(15.52,20.32)
  L4_SIGNAL w0.152: v1(15.52,20.32) 15.12,19.92 13.59,19.92 13.37,19.7 4.78,19.7
PL16B: length 11.6
  TOP w0.152: BGA.M5 v1(15.52,19.52)
  L4_SIGNAL w0.152: 4.78,19.44 13.44,19.44 13.76,19.13 13.78,19.13 13.78,19.12 15.12,19.12 v1(15.52,19.52)
PL16C: length 12.4
  TOP w0.152: BGA.L6 v1(16.32,20.32)
  BOTTOM w0.152: v1(16.32,20.32) 15.91,20.73 13.46,20.73 13.22,20.97 4.76,20.97
PL16D: length 14.7
  TOP w0.152: BGA.L7 v1(17.92,20.32)
  BOTTOM w0.152: v1(17.92,20.32) 17.02,20.32 16.73,20.61 16.73,21.25 16.71,21.26 16.71,21.28 16.48,21.51 13.52,21.51 13.23,21.22 4.76,21.22
PL17A: length 8
  TOP w0.152: 4.76,18.18 12.33,18.18 12.47,18.32 BGA.N1
PL17B: length 8.9
  TOP w0.152: 4.76,17.93 13.13,17.93 BGA.N2
PL17C: length 8
  TOP w0.152: BGA.P1 12.47,17.52 12.33,17.38 4.76,17.38
PL17D: length 8.9
  TOP w0.152: 4.76,17.13 13.13,17.13 BGA.P2
PL18A: length 9.7
  TOP w0.152: BGA.N3 v1(13.92,18.72)
  L3_SIGNAL w0.152: v1(13.92,18.72) 13.54,18.72 13.48,18.65 4.84,18.65
PL18B: length 10.6
  TOP w0.152: BGA.N4 v1(14.72,18.72)
  L3_SIGNAL w0.152: 4.84,18.4 13.49,18.4 13.57,18.32 14.32,18.32 v1(14.72,18.72)
PL18C: length 12.4
  TOP w0.152: BGA.M6 v1(16.32,19.52)
  BOTTOM w0.152: 4.76,19.37 13.38,19.37 13.62,19.12 15.92,19.12 v1(16.32,19.52)
PL18D: length 14
  TOP w0.152: BGA.M7 v1(17.92,19.52)
  BOTTOM w0.152: v1(17.92,19.52) 17.12,19.52 16.72,19.92 13.63,19.92 13.33,19.62 4.76,19.62
PL19A: length 9.7
  TOP w0.152: BGA.P3 v1(13.92,17.92)
  L3_SIGNAL w0.152: v1(13.92,17.92) 13.54,17.92 13.44,17.82 4.84,17.82
PL19B: length 10.6
  TOP w0.152: BGA.P4 v1(14.72,17.92)
  L3_SIGNAL w0.152: 4.84,17.52 14.32,17.52 v1(14.72,17.92)
PL19C: length 8
  TOP w0.152: 4.76,16.58 12.33,16.58 12.47,16.72 BGA.R1
PL19D: length 8.9
  TOP w0.152: BGA.R2 13.13,16.33 4.76,16.33
PL21A: length 8
  TOP w0.152: BGA.T1 12.47,15.92 12.33,15.78 4.76,15.78
PL21B: length 8.9
  TOP w0.152: BGA.T2 13.13,15.53 4.76,15.53
PL21C: length 11.6
  TOP w0.152: BGA.N5 v1(15.52,18.72)
  L4_SIGNAL w0.152: 4.78,18.07 13.36,18.07 13.61,18.32 15.12,18.32 v1(15.52,18.72)
PL21D: length 13.1
  TOP w0.152: BGA.N6 v1(16.32,18.72)
  L4_SIGNAL w0.152: 4.78,17.81 13.29,17.81 13.59,17.51 15.11,17.51 15.13,17.53 15.68,17.53 15.91,17.76 15.91,18.31 v1(16.32,18.72)
PL22A: length 8
  TOP w0.152: 4.76,14.98 12.33,14.98 12.47,15.12 BGA.U1
PL22B: length 8.9
  TOP w0.152: 4.76,14.73 13.13,14.73 BGA.U2
PL22C: length 9.7
  TOP w0.152: BGA.R3 v1(13.92,17.12)
  L3_SIGNAL w0.152: v1(13.92,17.12) 13.54,17.12 13.47,17.05 4.84,17.05
PL22D: length 10.6
  TOP w0.152: BGA.R4 v1(14.72,17.12)
  L3_SIGNAL w0.152: 4.84,16.79 13.5,16.79 13.57,16.72 14.32,16.72 v1(14.72,17.12)
PL23A: length 9.7
  TOP w0.152: BGA.T3 v1(13.92,16.32)
  L3_SIGNAL w0.152: 4.84,16.25 13.47,16.25 13.54,16.32 v1(13.92,16.32)
PL23B: length 10.6
  TOP w0.152: BGA.T4 v1(14.72,16.32)
  L3_SIGNAL w0.152: 4.84,16 13.5,16 13.57,15.92 14.32,15.92 v1(14.72,16.32)
PL23C: length 8
  TOP w0.152: BGA.V1 12.47,14.32 12.33,14.18 4.76,14.18
PL23D: length 8.9
  TOP w0.152: BGA.V2 13.13,13.93 4.76,13.93
PL24A: length 10.6
  TOP w0.152: BGA.V3 v1(13.92,14.72)
  L3_SIGNAL w0.152: v1(13.92,14.72) 14.17,14.47 14.17,4.78
PL24B: length 10.6
  TOP w0.152: BGA.V4 v1(14.72,14.72)
  L3_SIGNAL w0.152: v1(14.72,14.72) 14.42,14.42 14.42,4.78
PL24C: length 11.6
  TOP w0.152: BGA.P5 v1(15.52,17.92)
  BOTTOM w0.152: 4.77,17.82 13.22,17.82 13.52,17.53 15.12,17.53 15.51,17.92 v1(15.52,17.92)
PL24D: length 12.4
  TOP w0.152: BGA.P6 v1(16.32,17.92)
  BOTTOM w0.152: 4.77,18.07 13.28,18.07 13.53,18.33 15.91,18.33 v1(16.32,17.92)
PL25A: length 11.6
  TOP w0.152: BGA.T5 v1(15.52,16.32)
  L4_SIGNAL w0.152: v1(15.52,16.32) 15.12,15.92 13.57,15.92 13.35,16.14 4.78,16.14
PL25B: length 11.6
  TOP w0.152: BGA.R5 v1(15.52,17.12)
  L4_SIGNAL w0.152: 4.78,16.39 13.42,16.39 13.75,16.72 15.12,16.72 v1(15.52,17.12)
PL25C: length 11.6
  TOP w0.152: BGA.U4 v1(14.72,15.52)
  L4_SIGNAL w0.152: 14.59,4.8 14.59,14.19 14.32,14.46 14.32,15.12 v1(14.72,15.52)
PL25D: length 11.6
  TOP w0.152: BGA.U5 v1(15.52,15.52)
  L4_SIGNAL w0.152: v1(15.52,15.52) 15.12,15.12 15.12,14.5 14.84,14.22 14.84,4.8
PR2A: length 10.8
  TOP w0.152: BGA.D17 v1(25.92,25.92)
  L4_SIGNAL w0.152: v1(25.92,25.92) 26.32,26.32 26.32,26.92 25.96,27.28 25.96,35.84
PR2B: length 9.9
  TOP w0.152: BGA.C18 v1(26.72,26.72)
  L4_SIGNAL w0.152: 26.21,35.84 26.21,27.48 26.33,27.37 26.33,27.36 26.72,26.96 v1(26.72,26.72)
PR2C: length 12.4
  TOP w0.152: BGA.F15 v1(24.32,24.32)
  BOTTOM w0.152: 35.86,24.46 28.06,24.46 27.81,24.72 24.72,24.72 v1(24.32,24.32)
PR2D: length 12.4
  TOP w0.152: BGA.G15 v1(24.32,23.52)
  BOTTOM w0.152: v1(24.32,23.52) 24.72,23.92 27.76,23.92 28.05,24.21 35.86,24.21
PR3A: length 9
  TOP w0.152: BGA.C19 v1(27.52,26.72)
  L3_SIGNAL w0.152: v1(27.52,26.72) 27.8,26.72 27.93,26.59 35.86,26.59
PR3B: length 11.4
  TOP w0.152: BGA.E17 v1(25.92,25.12)
  L3_SIGNAL w0.152: 35.86,26.32 26.53,26.32 26.32,26.11 26.32,25.52 v1(25.92,25.12)
PR3C: length 11.6
  TOP w0.152: BGA.F16 v1(25.12,24.32)
  L4_SIGNAL w0.152: v1(25.12,24.32) 25.52,24.72 27.1,24.72 27.4,25.02 35.89,25.02
PR3D: length 10
  TOP w0.152: BGA.D18 v1(26.72,25.92)
  L4_SIGNAL w0.152: 35.89,25.27 27.37,25.27 v1(26.72,25.92)
PR4A: length 8.1
  TOP w0.152: BGA.B20 28.22,26.82 35.88,26.82
PR4B: length 8.1
  TOP w0.152: 35.88,26.57 28.17,26.57 BGA.C20
PR4C: length 14
  TOP w0.152: BGA.H14 v1(22.72,22.72)
  L4_SIGNAL w0.152: 35.89,22.79 28.84,22.79 28.51,23.12 23.12,23.12 v1(22.72,22.72)
PR4D: length 13.2
  TOP w0.152: BGA.H15 v1(23.52,22.72)
  L4_SIGNAL w0.152: 35.89,22.54 28.76,22.54 28.54,22.32 BGA.H15 v1(23.52,22.72)
PR5A: length 9.2
  TOP w0.152: BGA.D19 v1(27.52,25.92)
  L3_SIGNAL w0.152: v1(27.52,25.92) 28.07,25.37 35.89,25.37
PR5B: length 10.9
  TOP w0.152: BGA.F17 v1(25.92,24.32)
  L3_SIGNAL w0.152: 35.89,25.11 27.51,25.11 27.12,24.72 26.32,24.72 v1(25.92,24.32)
PR5C: length 8
  TOP w0.152: 35.86,25.38 28.34,25.38 28.2,25.52 BGA.D20
PR5D: length 8.9
  TOP w0.152: 35.88,25.12 27.52,25.12 BGA.E19
PR6A: length 11.6
  TOP w0.152: BGA.G16 v1(25.12,23.52)
  L4_SIGNAL w0.152: v1(25.12,23.52) 25.51,23.91 26.88,23.91 26.89,23.91 26.92,23.91 27.26,23.56 35.88,23.56
PR6B: length 9.9
  TOP w0.152: BGA.F18 v1(26.72,24.32)
  L4_SIGNAL w0.152: v1(26.72,24.32) 26.96,24.32 27.17,24.1 27.18,24.1 27.46,23.82 35.88,23.82
PR6C: length 10.9
  TOP w0.152: BGA.G17 v1(25.92,23.52)
  L3_SIGNAL w0.152: v1(25.92,23.52) 26.32,23.92 27.28,23.92 27.61,23.59 35.91,23.59
PR6D: length 9.3
  TOP w0.152: BGA.E20 v1(27.52,24.32)
  L3_SIGNAL w0.152: 35.91,23.84 27.72,23.84 27.52,24.04 v1(27.52,24.32)
PR7A: length 8.9
  TOP w0.152: BGA.F19 27.52,23.52 35.88,23.52
PR7B: length 8
  TOP w0.152: BGA.F20 28.27,23.92 28.36,23.83 35.88,23.83
PR7C: length 13.2
  TOP w0.152: BGA.J14 v1(23.52,21.92)
  BOTTOM w0.152: v1(23.52,21.92) 23.92,22.32 25.34,22.32 25.57,22.09 35.89,22.09
PR7D: length 12.4
  TOP w0.152: BGA.J15 v1(24.32,21.92)
  BOTTOM w0.152: v1(24.32,21.92) 24.73,21.51 25.31,21.51 25.64,21.84 35.89,21.84
PR8A: length 9.3
  TOP w0.152: BGA.G19 v1(27.52,22.72)
  BOTTOM w0.152: 35.89,23.24 27.76,23.24 27.52,23 v1(27.52,22.72)
PR8B: length 11.7
  TOP w0.152: BGA.H17 v1(25.12,22.72)
  BOTTOM w0.152: v1(25.12,22.72) 25.52,23.12 27.28,23.12 27.66,23.49 35.89,23.49
PR8C: length 12.3
  TOP w0.152: BGA.H16 v1(24.32,22.72)
  L3_SIGNAL w0.152: 35.8,22.88 29.29,22.88 29.05,23.12 24.72,23.12 v1(24.32,22.72)
PR8D: length 8.1
  TOP w0.152: BGA.G20 v1(28.32,22.72)
  L3_SIGNAL w0.152: 35.8,22.63 29.11,22.63 29.02,22.72 v1(28.32,22.72)
PR9A: length 11
  TOP w0.152: BGA.H18 v1(25.92,22.72)
  L3_SIGNAL w0.152: 35.86,21.89 26.49,21.89 26.19,22.19 26.19,22.45 v1(25.92,22.72)
PR9B: length 10.6
  TOP w0.152: BGA.H19 v1(26.72,22.72)
  L3_SIGNAL w0.152: 35.86,22.14 26.6,22.14 26.45,22.29 26.45,22.45 v1(26.72,22.72)
PR9C: length 10.5
  TOP w0.152: 35.88,21.91 25.91,21.91 BGA.J17
PR9D: length 8
  TOP w0.152: 35.88,22.16 28.3,22.16 28.15,22.32 BGA.H20
PR10A: length 9.7
  TOP w0.152: BGA.J18 v1(26.72,21.12)
  L3_SIGNAL w0.152: 35.85,21.16 27.13,21.16 27.09,21.12 v1(26.72,21.12)
PR10B: length 11.5
  TOP w0.152: BGA.J16 v1(25.12,21.92)
  L3_SIGNAL w0.152: v1(25.12,21.92) 25.52,21.52 27.08,21.52 27.18,21.41 35.86,21.41
PR10C: length 13.2
  TOP w0.152: BGA.K14 v1(23.52,21.12)
  L4_SIGNAL w0.152: 35.89,21.25 27.31,21.25 27.05,21.52 23.92,21.52 v1(23.52,21.12)
PR10D: length 12.4
  TOP w0.152: BGA.K15 v1(24.32,21.12)
  L4_SIGNAL w0.152: v1(24.32,21.12) 24.72,20.72 27.07,20.72 27.35,21 35.88,21
PR11A: length 8.9
  TOP w0.152: 35.88,21.13 27.51,21.13 BGA.J19
PR11B: length 8
  TOP w0.152: BGA.J20 28.17,21.52 28.31,21.38 35.88,21.38
PR11C: length 10.7
  TOP w0.152: BGA.K17 v1(25.92,21.12)
  L3_SIGNAL w0.152: v1(25.92,21.12) 26.32,20.72 26.98,20.72 27.05,20.65 35.86,20.65
PR11D: length 9.7
  TOP w0.152: BGA.K18 v1(26.72,20.32)
  L3_SIGNAL w0.152: v1(26.72,20.32) 27,20.32 27.08,20.4 35.86,20.4
PR12A: length 8.9
  TOP w0.152: BGA.K19 27.51,20.33 35.88,20.33
PR12B: length 8
  TOP w0.152: 35.88,20.58 28.31,20.58 28.17,20.72 BGA.K20
PR12C: length 11.6
  TOP w0.152: BGA.K16 v1(25.12,21.12)
  BOTTOM w0.152: v1(25.12,21.12) 25.36,21.12 25.76,21.51 25.79,21.51 25.79,21.52 26.98,21.52 27.24,21.26 35.89,21.26
PR12D: length 10.8
  TOP w0.152: BGA.L17 v1(25.92,20.32)
  BOTTOM w0.152: 35.89,21.01 27.3,21.01 27.01,20.72 26.32,20.72 v1(25.92,20.32)
PR15A: length 8.9
  TOP w0.152: BGA.L19 27.51,19.53 35.88,19.53
PR15B: length 8
  TOP w0.152: BGA.L20 28.17,19.92 28.31,19.78 35.88,19.78
PR15C: length 13.9
  TOP w0.152: BGA.L14 v1(23.52,20.32)
  L3_SIGNAL w0.152: 35.88,19.35 27.22,19.35 26.99,19.12 24.06,19.12 23.92,19.26 23.92,19.92 v1(23.52,20.32)
PR15D: length 12.4
  TOP w0.152: BGA.L15 v1(24.32,20.32)
  L3_SIGNAL w0.152: v1(24.32,20.32) 24.72,19.92 26.97,19.92 27.29,19.61 35.88,19.61
PR16A: length 8
  TOP w0.152: 35.88,18.98 28.31,18.98 28.17,19.12 BGA.M20
PR16B: length 8.9
  TOP w0.152: 35.88,18.73 27.51,18.73 BGA.M19
PR16C: length 11.7
  TOP w0.152: BGA.L16 v1(25.12,20.32)
  BOTTOM w0.152: v1(25.12,20.32) 25.52,19.92 27.03,19.92 27.38,19.57 35.89,19.57
PR16D: length 10
  TOP w0.152: BGA.M18 v1(26.72,18.72)
  BOTTOM w0.152: 35.89,19.31 27.31,19.31 v1(26.72,18.72)
PR17A: length 11.5
  TOP w0.152: BGA.M17 v1(25.92,19.52)
  BOTTOM w0.152: 35.92,18.72 28.42,18.72 28.02,18.33 26.56,18.33 26.33,18.56 26.33,19.11 v1(25.92,19.52)
PR17B: length 8.6
  TOP w0.152: BGA.N20 v1(28.32,17.92)
  BOTTOM w0.152: 35.92,18.47 28.57,18.47 28.32,18.21 v1(28.32,17.92)
PR17C: length 13.7
  TOP w0.152: BGA.M16 v1(25.12,19.52)
  BOTTOM w0.152: v1(25.12,19.52) 25.51,19.13 25.51,16.97 25.76,16.73 27.08,16.73 27.22,16.87 35.82,16.87
PR17D: length 9.4
  TOP w0.152: BGA.N19 v1(27.52,17.92)
  BOTTOM w0.152: v1(27.52,17.92) 27.52,17.52 27.92,17.12 35.82,17.12
PR18A: length 10
  TOP w0.152: BGA.N18 v1(26.72,17.92)
  L4_SIGNAL w0.152: 35.86,18.53 27.55,18.53 26.94,17.92 v1(26.72,17.92)
PR18B: length 10.9
  TOP w0.152: BGA.N17 v1(25.92,18.72)
  L4_SIGNAL w0.152: v1(25.92,18.72) 26.31,18.33 26.99,18.33 27.45,18.79 35.86,18.79
PR18C: length 8
  TOP w0.152: 35.88,17.38 28.31,17.38 28.17,17.52 BGA.P20
PR18D: length 8.9
  TOP w0.152: BGA.P19 27.5,17.14 27.77,17.14 27.79,17.13 35.88,17.13
PR19A: length 9.9
  TOP w0.152: BGA.P18 v1(26.72,17.12)
  L3_SIGNAL w0.152: v1(26.72,17.12) 28.16,17.12 28.56,17.52 35.86,17.52
PR19B: length 8.9
  TOP w0.152: BGA.R20 v1(28.32,16.32)
  L3_SIGNAL w0.152: v1(28.32,16.32) 28.32,16.92 28.67,17.27 35.86,17.27
PR19C: length 12.4
  TOP w0.152: BGA.M15 v1(24.32,19.52)
  L4_SIGNAL w0.152: v1(24.32,19.52) 24.72,19.12 26.85,19.12 26.86,19.13 26.88,19.13 27.16,19.41 35.88,19.41
